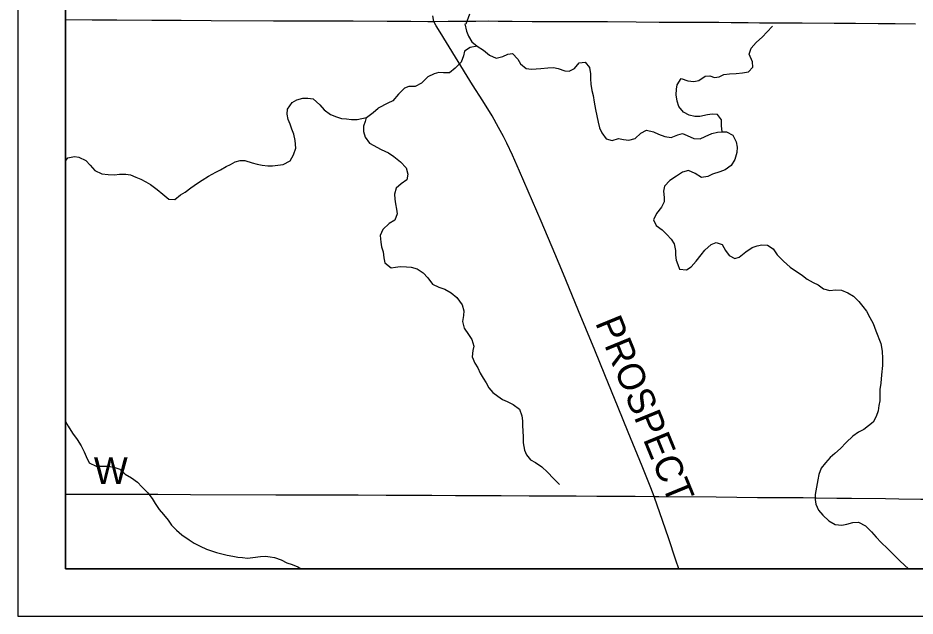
# Model space of a CAD drawing. Extents: x -17 to 88, y -5 to 22.
# Drawn here: x -17.26 to -15.367, y 14 to 15.263 of the extents above; entities that cross this region are included whole.
import ezdxf

# ---------------------------------------------------------------- set-up
doc = ezdxf.new("R2010")
doc.units = 0
for name, color, linetype in [('Default', 7, 'Continuous'), ('GM_X_County_Road', 7, 'Continuous'), ('GM_X_County_Road_Text', 7, 'Continuous'), ('GM_X_Minor_River', 7, 'Continuous'), ('GM_X_Township_Road', 7, 'Continuous'), ('SH_Data', 7, 'Continuous')]:
    doc.layers.add(name, color=color, linetype=linetype)

msp = doc.modelspace()

# ---------------------------------------------------------------- linework, layer by layer
at = {"layer": 'Default'}
msp.add_lwpolyline([(-17.1602, 20.9), (-10.3602, 20.9), (-10.3602, 14.1), (-17.1602, 14.1)], close=True, dxfattribs=at)
at = {"layer": 'GM_X_County_Road'}
for points in [[(-16.3824, 15.2559), (-16.3847, 15.2678)], [(-15.9175, 14.2528), (-15.9244, 14.2707), (-15.9431, 14.3168), (-15.9727, 14.3887), (-15.9939, 14.4404), (-16.0219, 14.5095), (-16.0428, 14.5614), (-16.0618, 14.6073), (-16.0772, 14.6447), (-16.0912, 14.6792), (-16.1089, 14.7223), (-16.1269, 14.7654), (-16.1563, 14.8339), (-16.202, 14.9394), (-16.2169, 14.9736), (-16.2284, 14.9991), (-16.2353, 15.013), (-16.2458, 15.0321), (-16.2598, 15.0563), (-16.2791, 15.0882), (-16.3008, 15.1223), (-16.3368, 15.1804), (-16.3695, 15.2332), (-16.3774, 15.2466), (-16.3824, 15.2559)], [(-17.1602, 14.2574), (-17.1265, 14.2575), (-17.0643, 14.2575), (-16.9648, 14.2572), (-16.8964, 14.2571), (-16.7161, 14.2564), (-16.6136, 14.2562), (-16.5421, 14.2558), (-16.483, 14.2554), (-16.4364, 14.2552), (-16.3867, 14.2551), (-16.3369, 14.2549), (-16.2903, 14.2548), (-16.2406, 14.2546), (-16.1815, 14.2542), (-16.1473, 14.2541), (-16.082, 14.2538), (-16.0385, 14.2535), (-15.9577, 14.2531), (-15.9175, 14.2528)], [(-15.8658, 14.1), (-15.8718, 14.1179), (-15.8875, 14.1651), (-15.9054, 14.2181), (-15.9166, 14.2504), (-15.9175, 14.2528)], [(-15.9175, 14.2528), (-15.908, 14.2528), (-15.7868, 14.2515), (-15.6997, 14.2507), (-15.6593, 14.2504), (-15.6376, 14.2503), (-15.6034, 14.2501), (-15.5754, 14.2496), (-15.5319, 14.2489), (-15.5009, 14.2487), (-15.4294, 14.2481), (-15.4014, 14.2476), (-15.3548, 14.2468), (-15.3331, 14.2466), (-15.3018, 14.2465), (-15.275, 14.2465)]]:
    msp.add_lwpolyline(points, dxfattribs=at)
at = {"layer": 'GM_X_Minor_River'}
for points in [[(-16.3145, 15.2511), (-16.3067, 15.2718)], [(-16.3172, 15.251), (-16.3136, 15.2353), (-16.3095, 15.2247), (-16.3025, 15.2128), (-16.2908, 15.2036), (-16.278, 15.1951), (-16.2648, 15.1847), (-16.2509, 15.1785), (-16.2372, 15.1818), (-16.2261, 15.187), (-16.2163, 15.188), (-16.205, 15.1761), (-16.1998, 15.1662), (-16.1878, 15.1566), (-16.1764, 15.1553), (-16.1665, 15.1556), (-16.1571, 15.1567), (-16.1422, 15.158), (-16.1301, 15.1587), (-16.1203, 15.1567), (-16.1063, 15.1512), (-16.0968, 15.1511), (-16.0858, 15.1567), (-16.0758, 15.1684), (-16.0633, 15.1701), (-16.0543, 15.1586), (-16.0521, 15.1453), (-16.0519, 15.1347), (-16.0512, 15.1237), (-16.0491, 15.11), (-16.0462, 15.0993), (-16.044, 15.0856), (-16.0415, 15.0701), (-16.0386, 15.0567), (-16.0361, 15.0434), (-16.0328, 15.0312), (-16.0284, 15.0206), (-16.0187, 15.0079), (-16.0062, 15.0044), (-15.9929, 15.0084), (-15.9826, 15.0068), (-15.9709, 15.0052), (-15.9576, 15.0088), (-15.9457, 15.0197), (-15.9335, 15.0264), (-15.9188, 15.0225), (-15.9082, 15.0178), (-15.895, 15.0128), (-15.8814, 15.0107), (-15.868, 15.0167), (-15.8581, 15.0192), (-15.848, 15.0149), (-15.834, 15.0087), (-15.8203, 15.0082), (-15.8097, 15.013), (-15.796, 15.019), (-15.7838, 15.0219), (-15.7743, 15.0229), (-15.7648, 15.0228), (-15.7516, 15.0155), (-15.7446, 15.0013), (-15.7428, 14.9903), (-15.7433, 14.9789), (-15.7476, 14.9642), (-15.7549, 14.9513), (-15.7676, 14.9424), (-15.7793, 14.9383), (-15.7942, 14.9331), (-15.8041, 14.9287), (-15.8178, 14.9262), (-15.831, 14.9346), (-15.8449, 14.9409), (-15.8578, 14.9376), (-15.8708, 14.9294), (-15.8842, 14.9196), (-15.8961, 14.9076), (-15.8977, 14.8977), (-15.8967, 14.8841), (-15.8968, 14.8746), (-15.9022, 14.8636), (-15.9126, 14.85), (-15.9192, 14.8372), (-15.9136, 14.8246), (-15.9004, 14.8158), (-15.8907, 14.8058), (-15.8817, 14.7958), (-15.8757, 14.7859), (-15.8728, 14.7718), (-15.8729, 14.7623), (-15.8711, 14.752), (-15.8674, 14.7425), (-15.8638, 14.7326), (-15.8494, 14.7309), (-15.8394, 14.7373), (-15.8287, 14.7493), (-15.8183, 14.7629), (-15.811, 14.7727), (-15.7976, 14.7851), (-15.787, 14.7892), (-15.7741, 14.7845)], [(-15.7743, 15.0229), (-15.7753, 15.0351), (-15.7752, 15.048), (-15.7842, 15.0591), (-15.7955, 15.06), (-15.8054, 15.0585), (-15.821, 15.0553), (-15.8316, 15.055), (-15.8441, 15.0578), (-15.8558, 15.0644), (-15.8659, 15.0759), (-15.8692, 15.0873), (-15.871, 15.101), (-15.8705, 15.1127), (-15.8692, 15.1222), (-15.8607, 15.135), (-15.8468, 15.1307), (-15.8339, 15.1287), (-15.8236, 15.1312), (-15.8103, 15.1402), (-15.8, 15.1409), (-15.7902, 15.1374), (-15.7807, 15.1388), (-15.7708, 15.1436), (-15.7586, 15.145), (-15.7446, 15.146), (-15.7313, 15.147), (-15.7184, 15.1495), (-15.7092, 15.1593), (-15.7102, 15.1703), (-15.7169, 15.1867), (-15.7129, 15.1996), (-15.7026, 15.2116), (-15.6892, 15.2236), (-15.68, 15.2334), (-15.6677, 15.2462)], [(-16.2908, 15.2036), (-16.3056, 15.2011), (-16.3178, 15.1928), (-16.3198, 15.183), (-16.3249, 15.1698), (-16.3379, 15.1574), (-16.3498, 15.1476), (-16.3619, 15.147), (-16.3718, 15.1478), (-16.382, 15.1453), (-16.3954, 15.139), (-16.4084, 15.1258), (-16.4217, 15.1187), (-16.435, 15.1185), (-16.4445, 15.1152), (-16.4572, 15.1024), (-16.4691, 15.0885), (-16.4794, 15.0829), (-16.4999, 15.0729)], [(-17.1602, 14.9605), (-17.1549, 14.9681), (-17.1412, 14.9707), (-17.1317, 14.969), (-17.1169, 14.9624), (-17.1075, 14.9524), (-17.0982, 14.9413), (-17.0834, 14.9343), (-17.0701, 14.9323), (-17.0568, 14.9321), (-17.0462, 14.9332), (-17.0329, 14.9334), (-17.023, 14.9318), (-17.0113, 14.9267), (-17.0011, 14.9228), (-16.9905, 14.9174), (-16.9803, 14.9112), (-16.9664, 14.9008), (-16.9543, 14.8912), (-16.9415, 14.8808), (-16.929, 14.8799), (-16.9171, 14.8893), (-16.9071, 14.8956), (-16.8953, 14.9046), (-16.8815, 14.9144), (-16.8716, 14.9204), (-16.8578, 14.929), (-16.8429, 14.9372), (-16.833, 14.9424), (-16.8211, 14.9495), (-16.8116, 14.9536), (-16.802, 14.9592), (-16.791, 14.9621), (-16.7815, 14.962), (-16.7663, 14.9569), (-16.7557, 14.9542), (-16.7451, 14.9521), (-16.7326, 14.9509), (-16.7231, 14.9512), (-16.7002, 14.954), (-16.6861, 14.9618), (-16.6787, 14.9743), (-16.674, 14.9883), (-16.6754, 15.0047), (-16.6783, 15.0176), (-16.6824, 15.0283), (-16.6861, 15.039), (-16.6898, 15.0486), (-16.6923, 15.06), (-16.6914, 15.0706), (-16.6818, 15.085), (-16.6718, 15.0906), (-16.6593, 15.0935), (-16.6483, 15.0941), (-16.6369, 15.0925), (-16.6229, 15.0798), (-16.6139, 15.0691), (-16.6004, 15.0594), (-16.5879, 15.0544), (-16.5773, 15.0512), (-16.5666, 15.05), (-16.5564, 15.0491), (-16.5442, 15.049), (-16.5343, 15.0508), (-16.5244, 15.0533), (-16.5103, 15.0635), (-16.4999, 15.0729)], [(-16.5253, 15.0531), (-16.5272, 15.0446), (-16.5311, 15.0348), (-16.5308, 15.0237), (-16.5275, 15.0111), (-16.5182, 14.9989), (-16.4936, 14.9854)], [(-16.4936, 14.9854), (-16.4785, 14.9784), (-16.4669, 14.9707), (-16.453, 14.9596), (-16.4413, 14.9466), (-16.4373, 14.9336), (-16.4397, 14.9215), (-16.4512, 14.9129), (-16.4619, 14.9039), (-16.4654, 14.8914), (-16.4648, 14.8803), (-16.4634, 14.8705), (-16.4612, 14.8594), (-16.4598, 14.8492), (-16.4648, 14.8359), (-16.4771, 14.8288), (-16.4905, 14.8164), (-16.4955, 14.8036), (-16.4945, 14.7895), (-16.4931, 14.78), (-16.4898, 14.7694), (-16.488, 14.7564), (-16.4863, 14.7458), (-16.4727, 14.7354), (-16.4632, 14.7368), (-16.4533, 14.7382), (-16.4405, 14.7373), (-16.4306, 14.7369), (-16.4177, 14.7333), (-16.4049, 14.7252), (-16.3952, 14.7141), (-16.3855, 14.7011), (-16.3723, 14.6945), (-16.3594, 14.6902), (-16.3462, 14.6828), (-16.3342, 14.6725), (-16.3226, 14.6575), (-16.3193, 14.6446), (-16.3202, 14.6347), (-16.3222, 14.6218), (-16.3186, 14.6078), (-16.3092, 14.5948), (-16.3025, 14.5844), (-16.2985, 14.5703), (-16.3001, 14.5609), (-16.3017, 14.5472), (-16.2962, 14.5343), (-16.2898, 14.5243), (-16.2846, 14.5129), (-16.2787, 14.5022), (-16.2723, 14.4926), (-16.2664, 14.4823), (-16.2578, 14.472), (-16.2476, 14.4647), (-16.2378, 14.4577), (-16.228, 14.4531), (-16.2152, 14.4465), (-16.202, 14.4369), (-16.1968, 14.4231), (-16.1958, 14.4121), (-16.1955, 14.4022), (-16.1943, 14.3787), (-16.194, 14.3658), (-16.1911, 14.3502), (-16.1871, 14.3406), (-16.1788, 14.3303), (-16.1679, 14.3245), (-16.1547, 14.3149), (-16.1427, 14.3041), (-16.1303, 14.2907), (-16.1176, 14.278)], [(-15.7741, 14.7845), (-15.767, 14.7722), (-15.7596, 14.7615), (-15.7475, 14.7553), (-15.738, 14.7583), (-15.7242, 14.7695), (-15.7105, 14.7785), (-15.7002, 14.7818), (-15.6907, 14.7844), (-15.6782, 14.7835), (-15.6665, 14.7754), (-15.6579, 14.7628), (-15.6448, 14.7497), (-15.6305, 14.7371), (-15.6045, 14.7193), (-15.5944, 14.7116), (-15.5819, 14.7047), (-15.5717, 14.6993), (-15.5604, 14.6912), (-15.5472, 14.6876), (-15.5347, 14.689), (-15.5222, 14.6881), (-15.5086, 14.6827), (-15.4969, 14.6753), (-15.486, 14.6642), (-15.4774, 14.6539), (-15.4695, 14.6439), (-15.4625, 14.6309), (-15.4558, 14.6176), (-15.4495, 14.6023), (-15.4392, 14.5756), (-15.4363, 14.5593), (-15.4357, 14.5437), (-15.4358, 14.5289), (-15.4376, 14.5096), (-15.4396, 14.4921), (-15.4413, 14.4788), (-15.4415, 14.4549), (-15.4432, 14.4447), (-15.4452, 14.4337), (-15.4491, 14.4216), (-15.4556, 14.4095), (-15.4652, 14.4016), (-15.4755, 14.3941), (-15.4862, 14.3882), (-15.4984, 14.3803), (-15.5122, 14.3668), (-15.5245, 14.354), (-15.5367, 14.3435), (-15.5463, 14.3349), (-15.5559, 14.3236), (-15.5655, 14.3127), (-15.5698, 14.2987), (-15.5722, 14.2877), (-15.575, 14.2725), (-15.5778, 14.257), (-15.5779, 14.246), (-15.5761, 14.2361), (-15.5709, 14.2235), (-15.5616, 14.2128), (-15.5488, 14.2009), (-15.5356, 14.1931), (-15.5216, 14.1919), (-15.5113, 14.1944), (-15.4984, 14.1977), (-15.4866, 14.198), (-15.4716, 14.1906), (-15.4592, 14.1779), (-15.4494, 14.1664), (-15.4385, 14.1557), (-15.425, 14.1427), (-15.4119, 14.1292), (-15.3995, 14.117), (-15.3894, 14.1077), (-15.3809, 14.1)], [(-17.1602, 14.4108), (-17.1546, 14.4011), (-17.1449, 14.3865), (-17.1352, 14.3731), (-17.1266, 14.3597), (-17.1203, 14.3467), (-17.1166, 14.3368), (-17.1099, 14.3234), (-17.0955, 14.3164), (-17.0791, 14.3166), (-17.0693, 14.3169), (-17.0556, 14.3141), (-17.0454, 14.3106), (-17.0337, 14.2998), (-17.0209, 14.2921), (-17.0081, 14.2828), (-16.9987, 14.2732), (-16.9863, 14.2602), (-16.9773, 14.2483), (-16.9705, 14.2376), (-16.9619, 14.2249), (-16.9533, 14.2146), (-16.9435, 14.2023), (-16.9361, 14.192), (-16.9255, 14.1816), (-16.9142, 14.1716), (-16.8991, 14.1608), (-16.8882, 14.1542), (-16.8757, 14.1476), (-16.8621, 14.1414), (-16.8409, 14.1343), (-16.8303, 14.1312), (-16.8186, 14.1284), (-16.8068, 14.1264), (-16.7962, 14.1247), (-16.7863, 14.1235), (-16.7761, 14.1226), (-16.7643, 14.1236), (-16.7487, 14.1261), (-16.7376, 14.1264), (-16.7282, 14.1252), (-16.7187, 14.1236), (-16.705, 14.1189), (-16.693, 14.1123), (-16.6816, 14.1087), (-16.6699, 14.104), (-16.6625, 14.1)]]:
    msp.add_lwpolyline(points, dxfattribs=at)
at = {"layer": 'GM_X_Township_Road'}
for points in [[(-17.1602, 15.2596), (-17.1038, 15.2593), (-17.0516, 15.259), (-16.9777, 15.2584), (-16.9157, 15.2584), (-16.8528, 15.258), (-16.7212, 15.2574), (-16.5528, 15.2569), (-16.4809, 15.2567), (-16.4308, 15.2563), (-16.3954, 15.256), (-16.3824, 15.2559)], [(-17.1602, 15.2596), (-17.1038, 15.2593), (-17.0516, 15.259), (-16.9777, 15.2584), (-16.9157, 15.2584), (-16.8528, 15.258), (-16.7212, 15.2574), (-16.5528, 15.2569), (-16.4809, 15.2567), (-16.4308, 15.2563), (-16.3954, 15.256), (-16.3824, 15.2559)], [(-16.3824, 15.2559), (-16.3525, 15.2563), (-16.329, 15.2563), (-16.2937, 15.2565), (-16.2664, 15.2568), (-16.2466, 15.2566), (-16.2175, 15.2566), (-16.1753, 15.256), (-16.1654, 15.2559)], [(-16.3824, 15.2559), (-16.3525, 15.2563), (-16.329, 15.2563), (-16.2937, 15.2565), (-16.2664, 15.2568), (-16.2466, 15.2566), (-16.2175, 15.2566), (-16.1753, 15.256), (-16.1654, 15.2559)], [(-16.1654, 15.2559), (-16.1236, 15.2556), (-16.0956, 15.2558), (-16.016, 15.2556), (-15.9559, 15.2552), (-15.9074, 15.2544), (-15.877, 15.2546), (-15.8386, 15.2544), (-15.805, 15.2542), (-15.781, 15.254), (-15.755, 15.2536), (-15.7335, 15.2534), (-15.7191, 15.2534), (-15.6951, 15.2527), (-15.6534, 15.2528), (-15.6205, 15.2531), (-15.605, 15.2531), (-15.5376, 15.2524), (-15.4926, 15.2524), (-15.4447, 15.2518), (-15.4093, 15.2514), (-15.3664, 15.251)], [(-16.1654, 15.2559), (-16.1236, 15.2556), (-16.0956, 15.2558), (-16.016, 15.2556), (-15.9559, 15.2552), (-15.9074, 15.2544), (-15.877, 15.2546), (-15.8386, 15.2544), (-15.805, 15.2542), (-15.781, 15.254), (-15.755, 15.2536), (-15.7335, 15.2534), (-15.7191, 15.2534), (-15.6951, 15.2527), (-15.6534, 15.2528), (-15.6205, 15.2531), (-15.605, 15.2531), (-15.5376, 15.2524), (-15.4926, 15.2524), (-15.4447, 15.2518), (-15.4093, 15.2514), (-15.3664, 15.251)]]:
    msp.add_lwpolyline(points, dxfattribs=at)
at = {"layer": 'SH_Data'}
for p, q in [((-17.2602, 21), (-17.2602, 14)), ((-17.1602, 20.9), (-17.1602, 14.1)), ((-17.1602, 14.1), (-10.3602, 14.1)), ((-17.2602, 14), (-10.2602, 14))]:
    msp.add_line(p, q, dxfattribs=at)

# ---------------------------------------------------------------- texts
at = {"layer": 'GM_X_County_Road_Text'}
for s, height, rotation, p in [('PROSPECT', 0.05682, 292.288, (-16.0427, 14.6198)), ('W', 0.0568, 0, (-17.1001, 14.2787))]:
    msp.add_text(s, height=height, rotation=rotation, dxfattribs=at).set_placement(p)

doc.saveas('drawing.dxf')
